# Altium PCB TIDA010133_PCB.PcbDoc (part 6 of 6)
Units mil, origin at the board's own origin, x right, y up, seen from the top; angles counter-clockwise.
Board outline 4100 x 6400 mil, 8 copper layers (Top Layer, Ground 1, Signal 1, Power 1, Ground 2, Signal 2, Power 2, Bottom Layer), stack 60.4 mil thick; 587 components, 322 nets, 1661 pads, 859 vias.
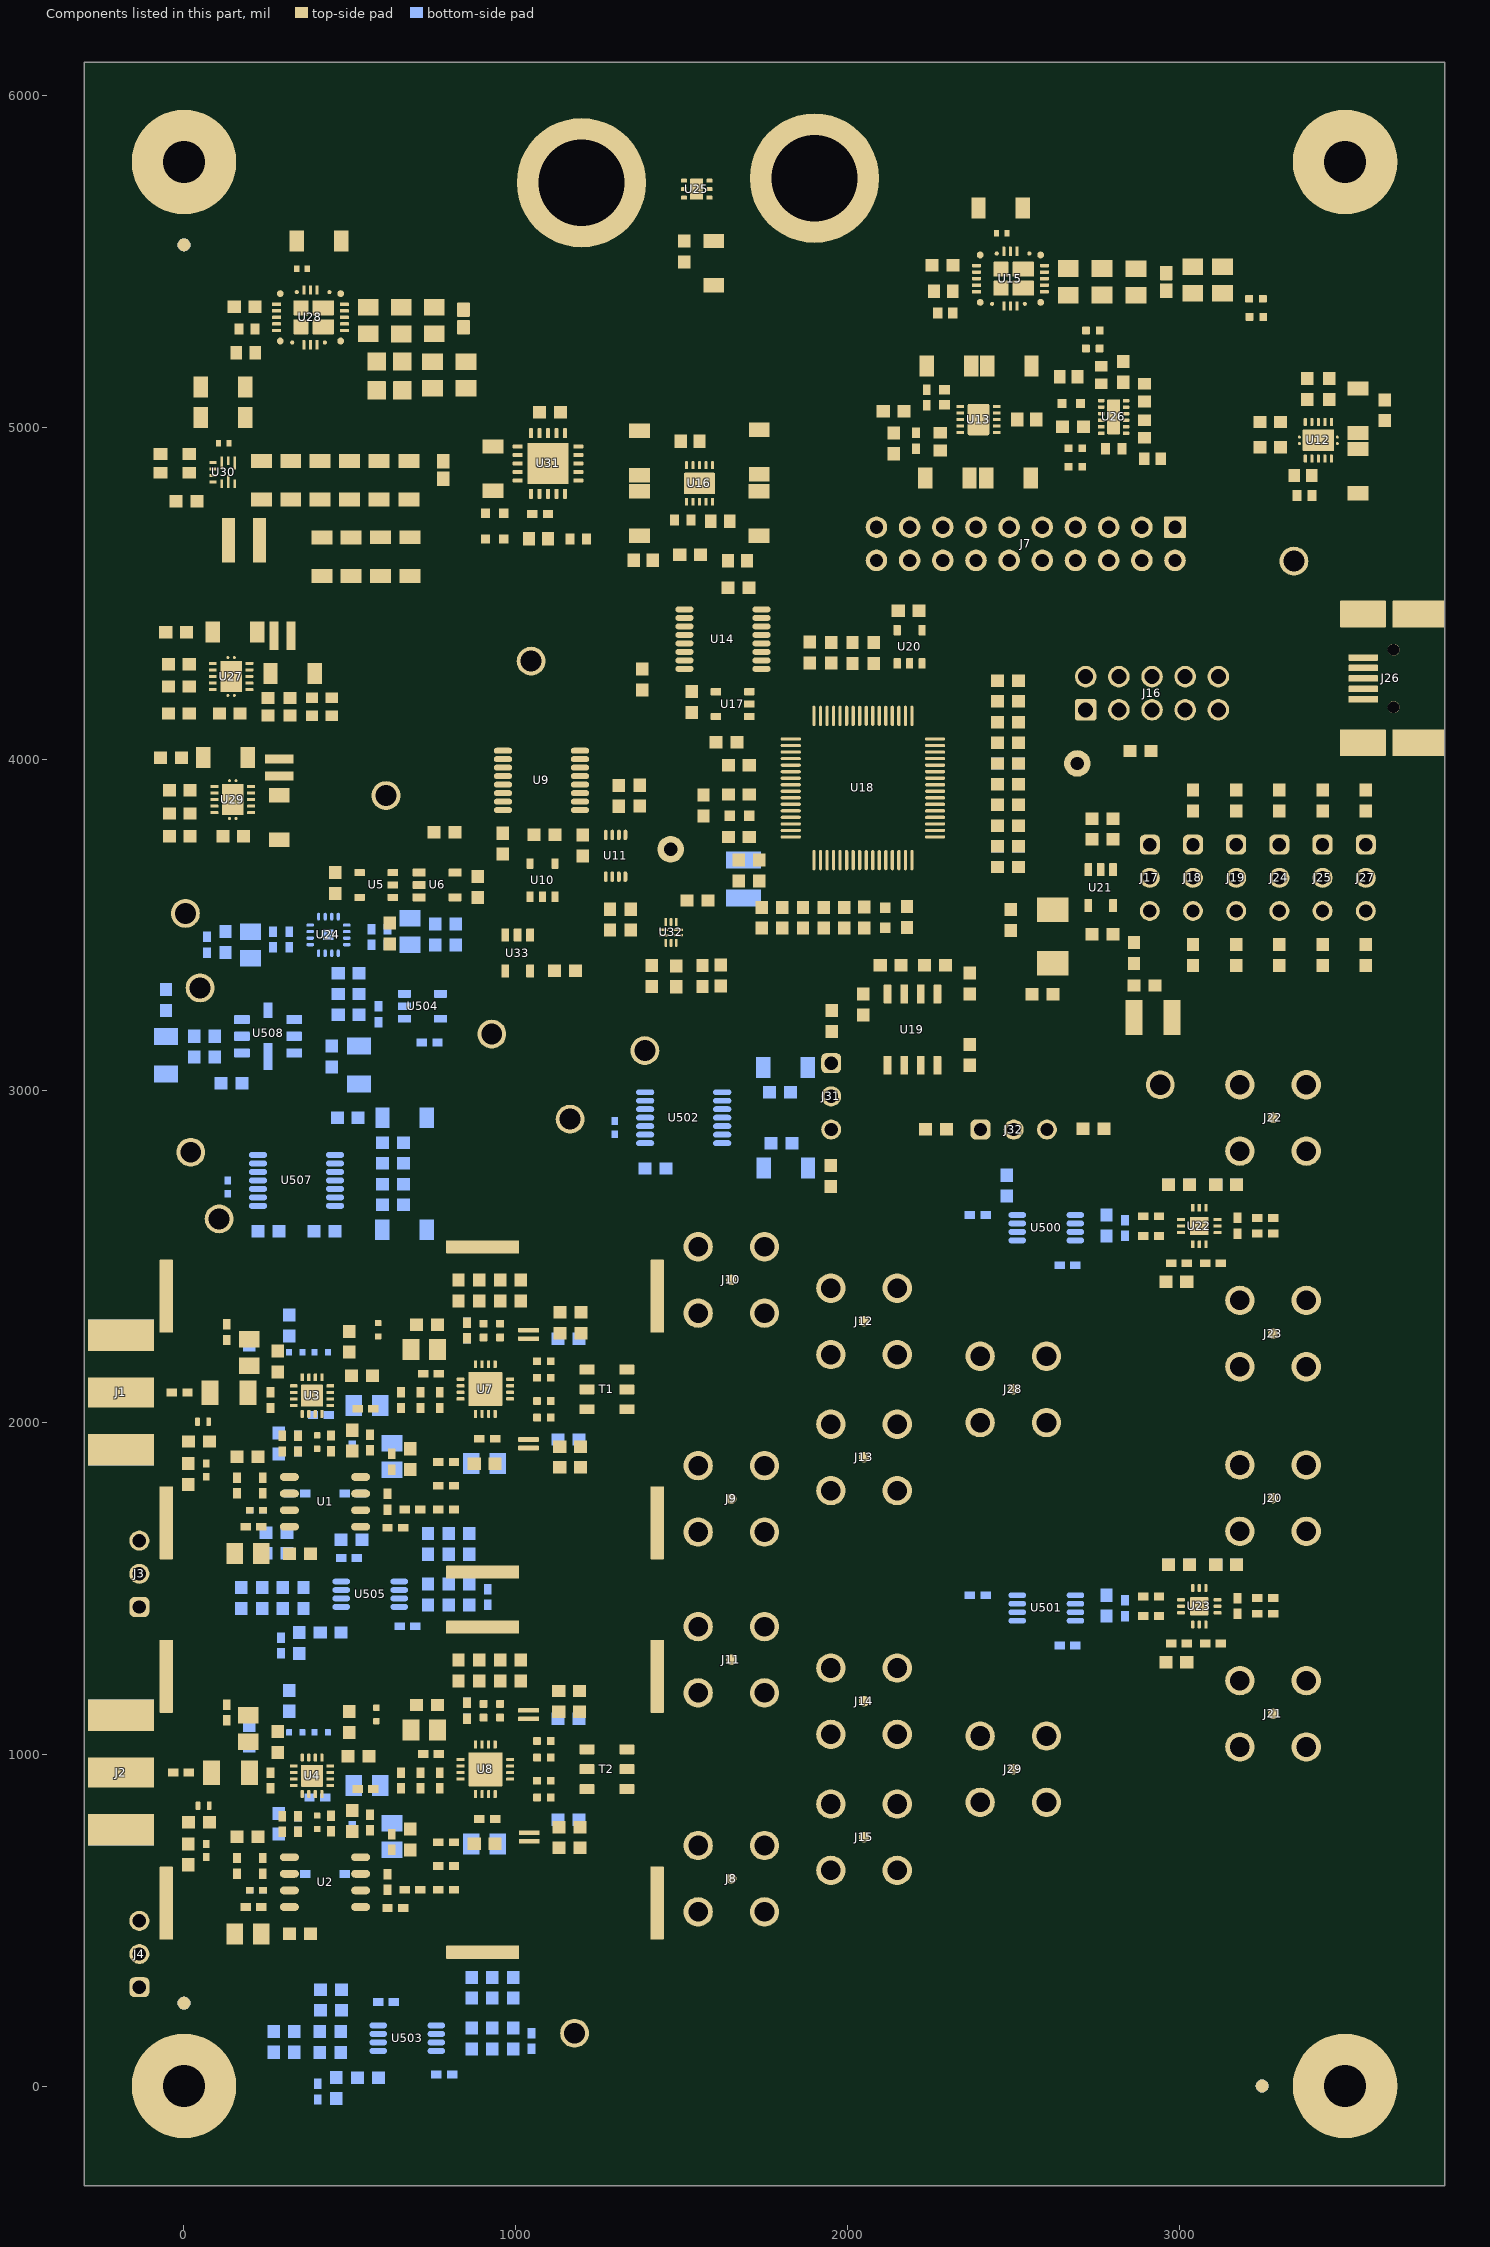
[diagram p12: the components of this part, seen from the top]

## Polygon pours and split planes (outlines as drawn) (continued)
-5VA_C on Bottom Layer "BOTTOM_LAYER_-5VA_C_P52956" (solid, remove dead copper, pour order 52956): 440.15,1514.5 422.78,1531.87 422.78,1661.81 431.2,1670.22 489.4,1670.22 495.95,1663.66 495.95,1559.31 503.46,1551.81 503.46,1517.34 500.62,1514.5
+5VA_LMH6518_1 on Bottom Layer "BOTTOM_LAYER_+5VA_LMH6518_1_P52954" (solid, remove dead copper, pour order 52954): 794.49,2169.85 824.25,2169.85 831.96,2162.14 870.59,2162.14 880.21,2171.76 880.21,2269.39 875.52,2274.08 789.16,2274.08 782.88,2267.8 782.88,2181.45
+5VA_LMH6518_2 on Bottom Layer "BOTTOM_LAYER_+5VA_LMH6518_2_P52953" (solid, remove dead copper, pour order 52953): 794.49,1023.59 824.25,1023.59 831.96,1015.88 870.59,1015.88 880.21,1025.5 880.21,1123.14 875.52,1127.82 789.17,1127.82 782.88,1121.54 782.88,1035.2
-5VA_C on Bottom Layer "BOTTOM_LAYER_-5VA_C_P52952" (solid, remove dead copper, pour order 52952): 534.74,295.76 541.67,302.69 598.33,302.69 609.29,291.7 609.29,222.3 616.08,215.51 616.08,179.53 612.49,175.94 552.94,175.94 534.74,194.15
+5VA_C on Bottom Layer "BOTTOM_LAYER_+5VA_C_P52950" (solid, remove dead copper, pour order 52950): 602.86,1444.55 609.04,1450.73 675.82,1450.73 678.92,1447.63 678.92,1421.8 670.04,1412.93 670.04,1337.83 661.16,1328.96 614.86,1328.96 602.86,1340.95
-5VA_C on Bottom Layer "BOTTOM_LAYER_-5VA_C_P52951" (solid, remove dead copper, pour order 52951): 2661.41,1409.23 2712.78,1409.23 2714.56,1407.46 2714.56,1253.78 2706.77,1245.99 2673.5,1245.99 2665.29,1254.2 2665.29,1350.03 2657.74,1357.58 2657.74,1405.56
+5VA_C on Bottom Layer "BOTTOM_LAYER_+5VA_C_P52949" (solid, remove dead copper, pour order 52949): 721.14,107.12 726.44,112.42 787.41,112.42 790.44,109.38 790.44,83.29 781.78,74.62 781.78,-5.48 774.69,-12.57 725.26,-12.57 721.14,-8.44
3P3USB on Bottom Layer "BOTTOM_LAYER_3P3USB_P52948" (solid, remove dead copper, pour order 52948): 2389.18,3963.19 2397.96,3954.41 2475.72,3954.41 2483.93,3962.63 2483.93,4024.59 2476.2,4032.32 2394.73,4032.32 2389.18,4026.77
GND on Bottom Layer "BOTTOM_LAYER_GND_P52947" (solid, remove dead copper, pour order 52947): 370.51,2006.73 405.93,2006.73 413.44,2014.24 413.44,2040.19 421.44,2048.18 421.44,2110.2 413.84,2117.79 356.83,2117.79 351.95,2112.91 351.95,2025.21
-5VA_C on Bottom Layer "BOTTOM_LAYER_-5VA_C_P52945" (solid, remove dead copper, pour order 52945): 2661.3,2555.38 2712.89,2555.38 2714.56,2553.71 2714.56,2437.76 2701.48,2424.68 2670.53,2424.68 2665.29,2429.92 2665.29,2496.28 2657.74,2503.83 2657.74,2551.82
GND on Bottom Layer "BOTTOM_LAYER_GND_P52946" (solid, remove dead copper, pour order 52946): 370.51,860.47 395.69,860.47 398.09,862.88 398.09,878.58 421.44,901.93 421.44,963.94 413.84,971.54 356.83,971.54 351.95,966.65 351.95,878.95
+5VA_TLV3605_2 on Bottom Layer "BOTTOM_LAYER_+5VA_TLV3605_2_P52944" (solid, remove dead copper, pour order 52944): 3008.66,1550.01 3057.91,1550.01 3066.8,1558.9 3066.81,1622.75 3052.27,1637.28 3012.69,1637.28 3000.57,1625.17 3000.57,1558.1
+5VA_TLV3605_1 on Bottom Layer "BOTTOM_LAYER_+5VA_TLV3605_1_P52943" (solid, remove dead copper, pour order 52943): 3010.87,2697.52 3061.33,2697.52 3066.8,2702.99 3066.81,2769.01 3052.27,2783.54 3012.69,2783.54 3000.57,2771.42 3000.57,2707.82
2.5V_DACREF1 on Bottom Layer "BOTTOM_LAYER_2.5V_DACREF1_P52942" (solid, remove dead copper, pour order 52942): 674.02,1689.78 669.18,1684.94 669.18,1647.29 680.47,1636 749.04,1636 759.05,1646.01 759.05,1685.94 755.21,1689.78
+2.5VA_1 on Power 1 "POWER_1_+2.5VA_1_P52907" (solid, remove dead copper, pour order 52907): 1527.46,2779.05 1730.18,2779.05 1730.18,3373.4 1464.3,3639.28 1197.72,3639.28 1197.72,3108.79
+8VA on Power 1 "Power-+8VA" (solid, remove dead copper, pour order 52916): 33 vertices, not listed, extent -300,-300 1876,5091.13
-5VA on Power 1 "POWER_1_-5VA_P52981" (solid, remove dead copper, pour order 52981): 46 vertices, not listed, extent 225.89,-300 3800,5015.49
+3P3VD on Power 1 "Power-+3P3VD" (solid, remove dead copper, pour order 52918): 44 vertices, not listed, extent 1459,1152.89 3800,5368.63
+12VA on Power 1 "POWER_1_+12VA_P52917" (solid, remove dead copper, pour order 52917): 18 vertices, not listed, extent -300,5281.57 3800,6100
-3.3VA on Power 1 "Power--3.3VA" (solid, remove dead copper, pour order 52915): 41 vertices, not listed, extent 485.59,838.53 2133.79,4776.43
-2.5VA on Power 1 "Power--2.5VA" (solid, remove dead copper, pour order 52914): 22 vertices, not listed, extent -300,2727.98 2701.64,5303.74
VREGIN on Power 1 "POWER_1_VREGIN_P52913" (solid, remove dead copper, pour order 52913): 2122.2,3612.88 2149.75,3585.33 2942.2,3585.33 2969.75,3612.88 2969.75,3672.8 2957.46,3685.08 2638.55,3685.08 2609.13,3714.5 2609.13,4391.89 2558.31,4442.7 1972.96,4442.7 1669.88,4139.61 1669.88,3816.74 1873.73,3612.88
+3P3VD on Power 1 "POWER_1_+3P3VD_P52912" (solid, remove dead copper, pour order 52912): 843.9,1873.49 1185.95,1873.49 1227,1832.44 1227,1559.95 1227,1246.41 1227,656.49 1189.84,619.33 783.38,619.33 762.89,639.82 762.89,1666.54 831.44,1735.09 831.15,1860.75
-5VA_C on Power 1 "POWER_1_-5VA_C_P52911" (solid, remove dead copper, pour order 52911): 2501.72,1265.56 2608.64,1158.64 2823.48,1158.64 2854.94,1190.1 2854.94,2376.61 2701.59,2529.96 2518.77,2529.96 2501.72,2512.91
LM27762_IN on Power 1 "Power-LM27762_IN" (solid, remove dead copper, pour order 52910): 22 vertices, not listed, extent 2221.71,4773.87 3202.89,5610
+5.5V_IN_TPS7A94 on Power 1 "POWER_1_+5.5V_IN_TPS7A94_P52909" (solid, remove dead copper, pour order 52909): 17 vertices, not listed, extent -79.19,3854.7 626.89,5084.15
+5VA_C on Power 1 "POWER_1_+5VA_C_P52908" (solid, remove dead copper, pour order 52908): 2476.06,2655.64 2476.06,1501.03 2454.48,1479.45 2217.62,1479.45 2174.41,1522.65 2174.41,2675.78 2202.17,2703.54 2428.16,2703.54
+5VA on Power 2 "POWER_2_+5VA_P52935" (solid, remove dead copper, pour order 52935): 62 vertices, not listed, extent -58.98,264.7 2999.9,5111.69
+2.5VA on Power 2 "Power/Ground 2-+2.5VA" (solid, remove dead copper, pour order 52934): 19 vertices, not listed, extent -300,2464.85 3800,6100
-5VA_C on Power 2 "POWER_2_-5VA_C_P52933" (solid, remove dead copper, pour order 52933): 33 vertices, not listed, extent -300,-300 2877.85,1702.77
2.5V_DACREF1 on Power 2 "POWER_2_2.5V_DACREF1_P52932" (solid, remove dead copper, pour order 52932): 59 vertices, not listed, extent -294.45,10.39 878.71,3364.85
+5VA_C on Power 2 "POWER_2_+5VA_C_P52931" (solid, remove dead copper, pour order 52931): 641.31,0.09 711.37,-69.98 1446.01,-69.98 2188.09,-69.98 2447.41,189.34 2447.41,1254 2532.6,1339.19 2532.6,1577.96 2471.65,1638.9 2058.19,1638.9 2027.16,1607.87 2027.16,589.31 1682.23,244.38 689.5,244.38 641.31,196.18
1P8V_USB on Power 2 "POWER_2_1P8V_USB_P52930" (solid, remove dead copper, pour order 52930): 1405.82,3659.84 1405.82,3838.46 1627.96,4060.6 1627.96,4298.58 1657.51,4328.13 2319.87,4328.13 2362.2,4285.8 2362.2,3656.28 2344.3,3638.38 1427.16,3638.38
+3P3VD on Power 2 "POWER_2_+3P3VD_P52929" (solid, remove dead copper, pour order 52929): 20 vertices, not listed, extent 794,3499.54 1603.62,4329.27
-2.5VA on Power 2 "POWER_2_-2.5VA_P52928" (solid, remove dead copper, pour order 52928): 2395.34,5176 2488.72,5269.38 2914.38,5269.38 2965,5320 2965,5570.29 2910.29,5625 2144.95,5625 2026.43,5506.48 2026.43,5208.7 2059.13,5176
+5VA_LMH6518_2 on Power 2 "POWER_2_+5VA_LMH6518_2_P52927" (solid, remove dead copper, pour order 52927): 940.17,622.27 932.9,629.53 932.9,822.68 780.67,974.91 780.67,1165.29 859.33,1243.95 859.33,1318.55 872.79,1332.01 1263.58,1332.01 1288.56,1307.03 1288.56,951.8 1288.56,643.82 1267,622.27
+5VA_LMH6518_1 on Power 2 "POWER_2_+5VA_LMH6518_1_P52926" (solid, remove dead copper, pour order 52926): 1269.29,1771.49 1290.72,1792.92 1290.72,2454.26 1265.74,2479.24 874.95,2479.24 861.49,2465.78 861.49,2391.18 782.83,2312.52 782.83,2122.14 935.06,1969.91 935.06,1851.77 935.06,1784.82 948.39,1771.49
+2.5VA_1 on Power 2 "POWER_2_+2.5VA_1_P52925" (solid, remove dead copper, pour order 52925): 1690.77,2815.56 1697.1,2809.23 1697.1,2633.18 1686.45,2622.53 834.37,2622.53 698.76,2486.93 508.79,2486.93 446.97,2548.74 446.97,2799.21 463.33,2815.56
-2.5VA_1 on Power 2 "POWER_2_-2.5VA_1_P52924" (solid, remove dead copper, pour order 52924): 1712.86,3049.79 1734.78,3027.87 1734.78,2850.25 1716.4,2831.87 454.76,2831.87 446.63,2839.99 446.63,2956.3 492.08,3001.75 1399.4,3001.75 1447.44,3049.79
+8VA_BUF802_1 on Power 2 "POWER_2_+8VA_BUF802_1_P52923" (solid, remove dead copper, pour order 52923): 98.65,2364.96 98.65,2052.38 130.79,2020.23 406.59,2020.23 484.89,2098.53 484.89,2227.34 336.31,2375.91 109.6,2375.91
-3.3VA_BUF802_2 on Power 2 "POWER_2_-3.3VA_BUF802_2_P52922" (solid, remove dead copper, pour order 52922): 289.24,752.89 336.85,705.29 494.67,705.29 503.49,714.1 503.49,936.02 606.1,1038.63 606.1,1107.36 545.06,1168.4 390.04,1168.4 289.24,1067.6
3P3USB on Power 2 "POWER_2_3P3USB_P52921" (solid, remove dead copper, pour order 52921): 2382.28,3915.7 2406.42,3891.57 2742.93,3891.57 2768.09,3916.73 2768.09,4067.59 2751.28,4084.39 2416.98,4084.39 2382.28,4049.69
VBUS on Power 2 "POWER_2_VBUS_P52920" (solid, remove dead copper, pour order 52920): 2699.28,3655.91 2699.28,3725.29 2713.65,3739.66 2840.2,3739.66 2855.82,3724.03 2855.82,3658.8 2843.7,3646.68 2708.51,3646.68
-5VA_C on Signal 2 "SIGNAL_2_-5VA_C_P52941" (solid, remove dead copper, pour order 52941): 18 vertices, not listed, extent 621.25,2261.54 2718.23,3285.11
+5VA_C on Signal 2 "SIGNAL_2_+5VA_C_P52940" (solid, remove dead copper, pour order 52940): 774.16,3227.82 774.16,3106.45 820.97,3059.64 1319.13,3059.64 1756.66,2622.11 2475.52,2622.11 2507.09,2653.67 2507.09,3191.76 2459.87,3238.98 785.32,3238.98
+5VA_C on Signal 2 "SIGNAL_2_+5VA_C_P52939" (solid, remove dead copper, pour order 52939): 518.03,1386 506.03,1373.99 506.03,-23.87 548.74,-66.59 852.29,-66.59 874.49,-44.38 874.49,760.95 747.73,887.71 747.73,1342.57 704.3,1386
-5.5V_IN_TPS7A33 on Signal 2 "SIGNAL_2_-5.5V_IN_TPS7A33_P52937" (solid, remove dead copper, pour order 52937): 1090.91,4632.29 1125.61,4666.99 1125.61,5016.4 1109.61,5032.4 883.05,5032.4 824.15,4973.5 640.64,4973.5 597.03,4929.89 597.03,4816.95 553.01,4772.93 386.81,4772.93 372.16,4758.27 372.16,4643.63 383.5,4632.29
+12VA on Signal 2 "SIGNAL_2_+12VA_P52936" (solid, remove dead copper, pour order 52936): 1546.14,4946.99 1546.14,4908.53 1562.38,4892.29 1677.53,4892.29 1788.36,4892.29 1812.57,4916.5 1812.57,5061.47 1668.34,5205.7 1668.34,5815.85 1652.34,5831.85 1475.9,5831.85 1454.96,5810.91 1454.96,5038.16
TPS62913_IBB_IN on Signal 2 "SIGNAL_2_TPS62913_IBB_IN_P52938" (solid, remove dead copper, pour order 52938): 225.4,4757.48 256.49,4788.57 528.34,4788.57 549.98,4810.21 549.98,5230.15 535.94,5244.19 239.28,5244.19 169,5314.47 6.39,5314.47 -98.33,5209.74 -98.33,4777.88 -77.93,4757.48
GND on Ground 1 "Top Layer-GND" (solid, remove dead copper, pour order 52906): -300,6100 -300,-300 3800,-300 3800,6100 3796.44,6100
GND on Ground 2 "Top Layer-GND" (solid, remove dead copper, pour order 52919): -300,6100 -300,-300 3800,-300 3800,6100 3796.44,6100

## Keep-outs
Keep-Out Layer:
  the board outline again, w50
  text ".Layer_Name" at -723,-1798.49 h60

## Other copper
Top Layer:
  pour cut-out: 988.81,2454.02 980.1,2445.31 980.1,2397.43 989.24,2388.38 ccw(c990.91,2390.62) 990.91,2387.83 1053.49,2387.83 ccw(c1053.49,2408.81) 1074.47,2408.81 1074.47,2436.79 ccw(c1057.24,2436.79) 1057.24,2454.02
  pour cut-out: 1172.32,1111.44 1172.32,1097.31 1174.24,1095.39 1213.38,1095.39 1223,1105.01 1223,1116 1176.88,1116
  pour cut-out: 652.61,4636.35 645.61,4629.35 645.61,4593.35 651.61,4587.35 715.61,4587.35 718.61,4590.35 718.61,4631.35 713.61,4636.35 660.61,4636.35
  pour cut-out: 563.61,4637.35 556.61,4630.35 556.61,4594.35 562.61,4588.35 626.61,4588.35 629.61,4591.35 629.61,4632.35 624.61,4637.35 571.61,4637.35
  pour cut-out: 474.61,4636.35 467.61,4629.35 467.61,4593.35 473.61,4587.35 537.61,4587.35 540.61,4590.35 540.61,4631.35 535.61,4636.35 482.61,4636.35
  pour cut-out: 386.61,4637.35 379.61,4630.35 379.61,4594.35 385.61,4588.35 449.61,4588.35 452.61,4591.35 452.61,4632.35 447.61,4637.35 394.61,4637.35
  pour cut-out: -79.77,965.48 -79.77,621.96 -65.97,608.17 58.22,608.17 102.32,564.08 476.51,564.08 495.47,583.04 495.47,699.04 484.92,709.6 371.69,709.6 359.87,721.42 359.87,782.7 353.88,788.69 330.06,788.69 327.1,791.65 327.1,849.05 340.42,862.37 340.42,889.61 349.97,899.16 419.23,899.16 421.29,901.22 421.29,967.68 417.86,971.11 354.84,971.11 340.93,957.2 291.78,957.2 262.98,986 -59.25,986
  pour cut-out: -79.63,2111.74 -79.63,1768.22 -65.84,1754.42 58.36,1754.42 102.45,1710.33 476.64,1710.33 495.61,1729.3 495.61,1845.3 485.05,1855.85 371.83,1855.85 360.01,1867.67 360.01,1928.95 354.02,1934.94 330.2,1934.94 327.24,1937.9 327.24,1995.31 340.56,2008.63 340.56,2035.87 350.1,2045.41 419.37,2045.41 421.42,2047.47 421.42,2113.94 417.99,2117.37 354.97,2117.37 341.06,2103.46 291.91,2103.46 262.37,2133 -58.37,2133
  pour cut-out: 1222.3,1168.31 1222.3,1149.72 1210.74,1138.16 1163.77,1138.16 1163.77,1164.76 1171.18,1172.16
  pour cut-out: 1220.03,2318.64 1225.88,2312.79 1225.88,2285.58 1180.47,2285.58 1171.77,2276.88 1171.77,2302.94 1187,2318.17 1219.91,2318.17
  pour cut-out: 708.06,1205.26 780.28,1277.48
  pour cut-out: 579.86,749.35 579.86,872.34 589.41,881.89 589.41,906.59 586.02,909.98 586.02,950.73 576.66,960.08 548.23,960.08 541.69,966.63 541.69,1010.57 547,1015.88 940.64,1015.88 949.36,1024.61 949.36,1051.65 967.49,1069.78 967.49,1188.04 974.5,1195.04 1057.7,1195.04 1071.96,1180.78 1071.96,1125.86 1068.17,1122.06 1005.24,1122.06 994.76,1111.58 994.76,1054.01 967.59,1026.84 967.59,908.43 960.22,901.05 935.46,901.05 930.13,895.73 930.13,863.83 941.74,852.22 941.74,837.08 935.46,830.81 922.6,830.81 913.55,821.76 913.55,763.09 904.3,753.84 855.83,753.84 848.64,746.65 848.64,695.89 832.64,679.88 786.71,679.88 728.71,737.88 591.04,737.88 580.4,748.52
  pour cut-out: 579.86,1895.6 579.86,2018.6 589.41,2028.14 589.41,2052.85 586.02,2056.24 586.02,2096.98 576.66,2106.34 548.23,2106.34 541.69,2112.88 541.69,2156.83 547,2162.14 940.64,2162.14 949.36,2170.86 949.36,2197.9 967.49,2216.03 967.49,2334.29 974.5,2341.3 1057.7,2341.3 1071.96,2327.03 1071.96,2272.11 1068.17,2268.32 1005.24,2268.32 994.76,2257.84 994.76,2200.27 967.59,2173.1 967.59,2054.68 960.22,2047.31 935.46,2047.31 930.13,2041.98 930.13,2010.08 941.74,1998.48 941.74,1983.34 935.46,1977.06 922.59,1977.06 913.55,1968.02 913.55,1909.34 904.3,1900.09 855.83,1900.09 848.64,1892.91 848.64,1842.14 832.64,1826.14 786.71,1826.14 728.71,1884.14 591.04,1884.14 580.4,1894.77
  text "1" at 3057.15,-43 h60
  text ".Layer_Name" at -723,-1798.49 h60
Ground 1:
  text "2" at 3041.4,-48.72 h60
  text ".Layer_Name" at -711.37,-1800 h60
Power 1:
  text "4" at 3041.4,-49.98 h60
  text ".Layer_Name" at -705.64,-1802.34 h60
Ground 2:
  text "5" at 3037.62,-47.46 h60
  text ".Layer_Name" at -713.29,-1796.6 h60
Power 2:
  pour cut-out: 1678.07,4742.11 1626.27,4742.11 1624.07,4744.3 1624.07,4771.85 1643.51,4791.3 1656.45,4791.3 1664.99,4782.76 1678.53,4782.76 1690.31,4770.99 1690.31,4754.34
  text "7" at 3041.4,-48.72 h60
  text ".Layer_Name" at -714.24,-1796.59 h60
Signal 1:
  text "3" at 3043.92,-44.94 h60
  text ".Layer_Name" at -723,-1798.49 h60
Signal 2:
  text "6" at 3043.86,-51.2 h60
  text ".Layer_Name" at -723,-1798.49 h60
Bottom Layer:
  pour cut-out: 3000.34,2661.04 3000.34,2694.4 3004.96,2699.02 3031.15,2699.02 3040.94,2689.22 3040.94,2658.3 3038.19,2655.55 3004.58,2655.55 3000.98,2659.15
  pour cut-out: 3002.3,1503.62 3002.3,1536.98 3006.91,1541.59 3033.11,1541.59 3042.9,1531.8 3042.9,1500.88 3040.14,1498.12 3006.54,1498.12 3002.94,1501.72
  text "8" at 3072.48,-44.08 h60
  text ".Layer_Name" at -723,-1798.49 h60

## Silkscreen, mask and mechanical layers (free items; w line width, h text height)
Top Overlay:
  drawing of 294 lines, arcs and shapes, not listed
  text "+3.3VD" at 3255.38,4474.74 h30
  text "USB2ANY I/F" at 2673.79,4328.36 h30
  text "GND" at 996.34,4169.88 h30
  text "3P3USB" at 2791.99,3891.78 h30 r90
  text "+8VA" at 551.57,3772.24 h30
  text "1" at 3634.94,3723.53 h30
  text "1P8V_USB" at 1362.14,3623.21 h30
  text "3" at 3625.68,3524.78 h30
  text "GND" at 123.58,3497.81 h30 r90
  text "+5VA" at 169.8,3250.4 h30 r90
  text "-5VA" at 1044.14,3110.17 h30 r90
  text "GND" at 1507.45,3070.45 h30 r90
  text "GND" at 2904.21,2901.68 h30
  text "Prog." at 1573.75,2850.76 h25
  text "J25" at 1386.05,2849.36 h25
  text "J31" at 1477.84,2849.19 h25
  text "-3.3VA" at 1073.03,2794.19 h30
  text "0" at 1405.46,2785.11 h25
  text "0" at 1496.41,2785.11 h25
  text "FTDI" at 1584.53,2783.23 h25
  text "Prog." at 2562.09,2740.21 h25
  text "J18" at 2003.37,2738.84 h25
  text "Device" at 2306.12,2739.46 h25
  text "J19" at 2088.93,2738.22 h25
  text "J24" at 2172.62,2738.09 h25
  text "-2.5VA" at 140.54,2727.25 h30 r90
  text "1" at 1408.13,2725.85 h25
  text "USB2ANY" at 1582.08,2721.86 h25
  text "1" at 1497.64,2720.92 h25
  text "CH1_TRIGGER_OUTP" at 3524.51,2714.48 h30 r90
  text "D" at 543.46,2697.44 h25
  text "x" at 2023.66,2683.59 h25
  text "LMH6518" at 2268.37,2681.97 h25
  text "FTDI" at 2552.75,2681.06 h25
  text "0" at 2197.97,2679.85 h25
  text "0" at 2110.33,2679.16 h25
  text "1" at 2114.77,2615.6 h25
  text "0" at 2198.53,2615.6 h25
  text "LMH6518_CH1" at 2264.6,2614.07 h25
  text "0" at 2027.49,2612.83 h25
  text "USB2ANY" at 2551.32,2611.21 h25
  text "1" at 2031.24,2548.87 h25
  text "1" at 2115.92,2547.5 h25
  text "0" at 2197.83,2546.11 h25
  text "LMH6518_CH2" at 2264.98,2546.16 h25
  text "USB2ANY" at 2551.69,2542.27 h25
  text "+2.5VA" at 223.65,2535.92 h30 r90
  text "E" at 1325.44,2531.35 h25
  text "CH1" at -230.68,2403.32 h30
  text "E" at 1068.53,2382.91 h25
  text "F" at 1161.35,2197.69 h25
  text "D" at 621.17,2135.33 h25
  text "CH1_TRIGGER_OUTN" at 3522.62,2082.62 h30 r90
  text "F" at 1232.86,1773.29 h25
  text "J10: CH1_OUT+ / J9: CH1_OUT- / J12: CH1_OUT_T+ / J13: CH1_OUT_T- / J28: CH1_OUT_CM" at 2297,1571 h30
  text "CH2_TRIGGER_OUTP" at 3525.15,1551.34 h30 r90
  text "B" at 1301.09,1495.01 h25
  text "A" at 337.33,1474.61 h25
  text "B" at 1071.08,1281.08 h25
  text "CH2" at -235.04,1252.86 h30
  text "C" at 1170.62,1052.15 h25
  text "A" at 611.28,988.06 h25
  text "CH2_TRIGGER_OUTN" at 3520.39,941.41 h30 r90
  text "C" at 1213.4,617.33 h25
  text "J11: CH2_OUT+ / J8: CH2_OUT- / J14: CH2_OUT_T+ / J15: CH2_OUT_T- / J29: CH2_OUT_CM" at 2289,384 h30
  text "'.PRJ_Title'_REV.PCB_Rev" at 1856.1,152.9 h110
  text "GND" at 1142.81,36.72 h30
  text "CCA REV [ ]" at 389.98,-74.95 h60
  text "'.CCA REV'" at 899.22,-81.34 h110
  text "ESD REV [ ]" at 392.04,-197.65 h60
  text "'.ESD REV'" at 902.84,-199.15 h110
  text ".Layer_Name" at -723,-1798.49 h60
Bottom Overlay:
  circle w14: c2732.61,2626.44 r2.35
  circle w14: c2732.61,1480.18 r2.35
  circle w14: c1343.92,2825.17 r2.35
  circle w14: c539.1,104.9 r2.35
  circle w14: c621.3,3216.4 r2.35
  circle w14: c422.11,1445.25 r2.35
  circle w14: c519.38,3403.76 r2.35
  circle w14: c184.33,2621.02 r2.35
  circle w6: c334.65,258.66 r25
  circle w6: c163.69,345.93 r25
  lines w6: -4.08,1521.78 6,1531.87 132.72,1531.87 ; 108.77,3207.11 108.77,3242.13 ; 171.79,738.97 176.95,733.8 249.44,733.8 ; 176.32,1891.2 183.4,1884.13 247.34,1884.13 ; 198.77,1599.89 198.77,1606.95 205.85,1614.04 ; 297.19,350.63 297.19,279.99 281.69,264.49 141.65,264.49 126.58,279.56 126.58,488.45 141.76,503.63 279.19,503.63 297.19,485.63 297.19,416.63 ; 317.25,2175.86 317.25,2189.94 ; 318.62,1025.61 318.62,1046.98 ; 333.9,2032.49 341.19,2025.21 351.95,2025.21 ; 371.82,210.49 371.82,71.91 378.88,64.86 502.77,64.86 514.86,76.94 514.86,323.44 506.94,331.36 382.26,331.36 371.82,320.91 371.82,310.35 ; 400.02,3332.17 409.36,3332.17 427.01,3314.53 ; 441.14,902.83 441.14,963.53 ; 565.15,1394.34 565.15,1406.94 ; 619.39,3180.19 631.2,3168.38 631.2,3161.42 ; 631.22,3527.29 631.22,3586.77 ; 678.6,47.92 678.6,68.66 ; 696.05,1327.28 696.05,1351.75 ; 727.83,1710.94 727.83,1722.69 740.68,1735.54 887.22,1735.54 894.04,1728.72 ; 764.95,3545.52 764.95,3554.8 774.22,3564.07 ; 807.77,-9.47 807.77,3.39 ; 946.3,1531.45 964.97,1550.12 1089.91,1550.12 1101.96,1538.08
  text "G" at 173.19,333.8 h25
  text "G" at 344.15,246.54 h25
  text ".Layer_Name" at -723,-1798.49 h60
Top Paste:
  text ".Layer_Name" at -723,-1798.49 h60
Bottom Paste:
  text ".Layer_Name" at -723,-1798.49 h60
Top Solder:
  text ".Layer_Name" at -723,-1798.49 h60
  text ".Layer_Name" at -723,-1798.49 h60
Bottom Solder:
  text ".Layer_Name" at -723,-1798.49 h60
Drill Guide:
  text ".Layer_Name" at -723,-1798.49 h60
M1 Board Outline:
  the board outline again, w10
  text ".Layer_Name" at -723,-1798.49 h60
M2 Board Dimensions:
  rectangle: -1300,-1215 -1175,-1090
  rectangle: -1175,-1340 -800,-1215
  lines w7: -1300,-1215 -300,-1215 ; -1175,-1340 -1175,-1090 ; -1050,-1340 -1050,-1090 ; -800,-1340 -800,-1090 ; -550,-1340 -550,-1090 ; -1300,-1340 -300,-1340 -300,-1090 -1300,-1090 -1300,-1340
  lines w10: -300,-300 3800,-300 3800,6100 -300,6100 -300,-300
M3 3D STEP Top:
  text ".Layer_Name" at -723,-1798.49 h60
M4 3D STEP Bottom:
  text ".Layer_Name" at -723,-1798.49 h60
M5 Assembly Top:
  drawing of 156 lines, arcs and shapes, not listed
  text "R82" at 2258.54,5398.45 h20
  text "R80" at 2266.42,5333.8 h20
  text "R169" at 157.5,5286.43 h20
  text "R171" at 149.32,5214.59 h20
  text "R98" at 2641.27,5143.67 h20
  text "R99" at 2775.18,5130.21 h20 r90
  text "C114" at 2905.85,5067.23 h20 r90
  text "R87" at 2303.69,5062.27 h20 r90
  text "C53" at 2511.62,5010.64 h20
  text "C119" at 2906.82,4954.34 h20 r90
  text "C80" at 1494.19,4947.91 h20
  text "R83" at 2288.37,4931.49 h20 r90
  text "R90" at 2781.63,4924.07 h20
  text "R91" at 2900.06,4895.1 h20
  text "R178" at 25.14,4857.45 h20 r90
  text "R175" at -59.84,4856.03 h20 r90
  text "C22" at 3346.62,4843.28 h20
  text "C117" at 238.92,4807.17 h20 r90
  text "C126" at 500.26,4806.44 h20 r90
  text "C127" at 598.75,4806.45 h20 r90
  text "C118" at 326.13,4805.39 h20 r90
  text "C128" at 681.96,4805.05 h20 r90
  text "C125" at 418.43,4802.29 h20 r90
  text "R77" at 3352.34,4781.28 h20
  text "R108" at 1469.29,4708.33 h20
  text "R103" at 1582.34,4707.25 h20
  text "R177" at 1035.13,4653.51 h20
  text "R179" at 1155.85,4652.55 h20
  text "L16" at 151.13,4647.9 h20
  text "C69" at 1643.54,4589.49 h20
  text "C77" at 1362.28,4586.8 h20
  text "C133" at 328.15,4122.63 h20 r90
  text "R116" at 393.25,4122.63 h20 r90
  text "C132" at 262.08,4121.66 h20 r90
  text "R117" at 458.34,4120.69 h20 r90
  text "MP1" at 609.92,1571.72 h20
  text "MP2" at 601.29,417.99 h20
  text "COMPONENTS MARKED 'DNP' SHOULD NOT BE POPULATED." at -146.5,-1258.5 h60
  text "ASSEMBLY VARIANT:" at -147,-1374 h60
  text ".VariantName" at 889,-1374 h60
  text "PCB VIEWED FROM TOP SIDE" at -1528.5,-1595.67 h60
  text "BOARD #:" at 948,-1595.67 h60
  text ".PRJ_Number" at 1493.5,-1595.67 h60
  text "REV:" at 2338,-1595.67 h60
  text ".PCB_Rev" at 2629.5,-1595.67 h60
  text "SVN REV:" at 3176,-1595.67 h60
  text ".VersionControl_RevNumber" at 3682,-1595.67 h60
  text "TID #:" at 948,-1799 h60
  text ".TID" at 1493.5,-1799 h60
  text ".plot_File_Name" at -856.21,-1994.13 h50
  text "PLOT NAME =" at -1528.5,-2004.34 h60
  text "GENERATED    :" at 950,-2004.34 h60
  text ".Print_Date" at 1819.5,-2004.34 h60
  text ".Print_Time" at 2548.5,-2004.34 h60
  text "TEXAS INSTRUMENTS" at 3813,-2004.34 h60
M6 Assembly Bottom:
  circle w14: c174.68,3114.05 r2.05
  circle w14: c636.28,3216.53 r2.05
  lines w10: -1592.5,-1667.33 5009.5,-1667.33 ; -1590.5,-1870.67 5009.5,-1870.67 ; -184.5,-2080.5 -184.5,-1877.67 ; 437.5,-1667.33 437.5,-1464 ; 1277.5,-1667.33 1277.5,-1464 ; 2544.5,-2074 2544.5,-1464 ; 3433.5,-2074 5009,-2074 5009,-1464 -1592.5,-1464 -1592.5,-2074 1004.5,-2074 5009.5,-2074 5009.5,-1464
  text "COMPONENTS MARKED 'DNP' SHOULD NOT BE POPULATED." at 4802,-1258 h60
  text ".VariantName" at 3758,-1374 h60
  text "ASSEMBLY VARIANT:" at 4797,-1374 h60
  text ".VersionControl_RevNumber" at -264.5,-1596.17 h60
  text "SVN REV:" at 241.5,-1596.17 h60
  text ".PCB_Rev" at 788,-1596.17 h60
  text "REV:" at 1079.5,-1596.17 h60
  text ".PRJ_Number" at 1924,-1596.17 h60
  text "BOARD #:" at 2469.5,-1596.17 h60
  text "PCB VIEWED FROM BOTTOM SIDE" at 4946,-1596.17 h60
  text ".TID" at 1924,-1799.5 h60
  text "TID #:" at 2469.5,-1799.5 h60
  text ".plot_File_Name" at 4268.64,-1990.76 h50
  text "TEXAS INSTRUMENTS" at -395.5,-2004.84 h60
  text ".Print_Time" at 869,-2004.84 h60
  text ".Print_Date" at 1598,-2004.84 h60
  text "GENERATED    :" at 2467.5,-2004.84 h60
  text "PLOT NAME =" at 4946,-2004.84 h60
M9 Title Sheet:
  drawing of 57 lines, arcs and shapes, not listed
  text "1" at -560.16,7096.5 h70
  text "2" at 1935.5,7096.5 h70
  text "3" at 4424.84,7096.5 h70
  text "4" at 6931.51,7096.5 h70
  text "5" at 9430.5,7096.5 h70
  text "6" at 11935.5,7096.5 h70
  text "A" at -1716.5,5953.5 h70
  text "A" at 13083.5,5953.5 h70
  text "B" at -1716.5,3573.5 h70
  text "B" at 13083.5,3573.5 h70
  text "C" at -1716.5,1198.5 h70
  text "C" at 13083.5,1198.5 h70
  text "PROJECT TITLE:" at 10043.5,-662.5 h45
  text ".PRJ_Title" at 10093.5,-795.83 h70
  text "DESIGNED FOR:" at 10043.5,-963.5 h45
  text ".PRJ_Customer" at 10093.5,-1103.5 h70
  text "D" at -1716.5,-1171.5 h70
  text "D" at 13083.5,-1171.5 h70
  text "FILE NAME:" at 10043.5,-1263.5 h45
  text ".PCB_File_Name_No_Path" at 10093.5,-1383.5 h70
  text "Texas Instruments (TI) and/or its licensors do not warrant the accuracy or completeness of this specification" at 5074,-1545.34 h45
  text "ENGINEER:" at 10043.5,-1553.5 h45
  text "LAYOUT BY:" at 11548.5,-1553.5 h45
  text "or any information contained therein. TI and/or its licensors do not warrant that this design will meet" at 5029.01,-1658 h45
  text ".PRJ_Engineer" at 10093.5,-1708.49 h70
  text ".PCB_Layout" at 11599,-1708.49 h70
  text "the specifications, will be suitable for your application or fit for any particular purpose, or will operate in" at 5029.01,-1770.67 h45
  text "ALTIUM DESIGNER VERSION:" at 11548.5,-1863.5 h45
  text "an implementation. TI and/or its licensors do not warrant that the design is production worthy. You should" at 5029.01,-1883.33 h45
  text "completely validate and test your design implementation to confirm the system functionality for your application." at 5074,-1996 h45
  text ".print_Scale" at 10093.5,-1996.83 h70
  text ".Application_BuildNumber" at 11599,-1996.83 h70
  text "1" at -560.16,-2203.5 h70
  text "2" at 1935.5,-2203.5 h70
  text "3" at 4424.84,-2203.5 h70
  text "4" at 6931.51,-2203.5 h70
  text "5" at 9430.5,-2203.5 h70
  text "6" at 11935.5,-2203.5 h70
  text "WO#309716-9714-D" at 12055.73,-2203.93 h70
M10 Fab Notes:
  drawing of 205 lines, arcs and shapes, not listed
  text "FAB NOTES" at 4212.43,6395.78 h60
  text "1. BOARD DIMENSION IS : 4100MIL x 6400MIL" at 4201.05,6229.12 h60
  text "2. VENDOR MAY ADJUST SOLDERMASK WHEREVER SOLDERMASK PADS ARE THE SAME SIZE (1:1) AS PER THE MANUFACTURING CAPABILITIES AND ALL OTHER SOLDER MASK PADS SHALL NOT BE MODIFIED," at 4201.05,6070.77 h60
  text "PROVIDED NO ADJACENT COPPER IS EXPOSED AND NO CONFLICT IS PRODUCED WITH ANY STATED \"VIA TENTING/COVERING\" REQUIREMENTS." at 4320.16,5913.01 h60
  text "3. TRACES WITH 20 MIL TO BE 50 OHMS +/-10% SINGLE ENDED ON TOP LAYER (L1)." at 4201.27,5759.81 h60
  text "4. ALL 10MIL VIAS ARE TENTED ON TOP SIDE UNLESS OTHERWISE SOLDER MASK IS OPENED IN GERBER." at 4198.65,5594.68 h60
  text "5. TRACES WITH 11 MIL AND 6 MIL SPACING TO BE 90 OHMS +/-10% DIFFERENTIAL PAIR ON TOP LAYER (L1)." at 4205.39,5421.19 h60
  text "DESIGN INFORMATION" at 11082.02,5416.17 h60
  text "MIN. TRACK WIDTH:" at 10437.46,5284.05 h60
  text "6" at 11533.7,5284.05 h60
  text "MIL" at 11688.46,5284.05 h60
  text "6. ALL 7.874MIL VIAS ARE TENTED ON BOTTOM SIDE UNLESS OTHERWISE SOLDER MASK IS OPENED IN GERBER." at 4202.2,5256.45 h60
  text "6" at 11537.14,5166.32 h60
  text "MIN. CLEARANCE:" at 10437.46,5159.92 h60
  text "MIL" at 11688.46,5159.92 h60
  text "19.685" at 11330.9,5042.78 h60
  text "MIN. VIA PAD SIZE:" at 10437.46,5035.8 h60
  text "MIL" at 11688.46,5035.8 h60
  text "0.05mm (2MIL)" at 11132.46,4905.9 h60
  text "MINIMUM ANNULAR RING" at 10108.23,4897.67 h60
  text "EXTERNAL" at 11840.46,4897.67 h60
  text "PER" at 10308.23,4787.55 h60
  text "IPC-D-275 CLASS 2 LEVEL C" at 10528.23,4787.54 h60
  text "MIL, HOLES" at 12016.46,4687.07 h60
  text "+/-" at 11624,4678.48 h60
  text "+/-" at 12478,4678.48 h60
  text "REGISTRATION TOLERANCES:" at 10108.23,4677.42 h60
  text "METAL" at 11308,4677.42 h60
  text "5" at 11884.2,4677.42 h60
  text "3" at 12717.2,4677.42 h60
  text "MIL" at 12833.46,4677.42 h60
  text "HOLE SIZE TOLERANCE (UNLESS OTHERWISE SPECIFIED):" at 10108.23,4579.1 h60
  text "+/-" at 12478,4576.23 h60
  text "3" at 12717.2,4575.17 h60
  text "MIL" at 12833.46,4575.17 h60
  text "MATERIAL:" at 10033.46,4437.52 h60
  text "FR-4 High Tg" at 11019.9,4309 h60
  text "X" at 11764.92,4303.53 h60
  text "FR-4" at 12399.62,4303.93 h60
  text "FR-408" at 10454.46,4296.49 h60
  text "OTHER" at 11942.46,4296.49 h60
  text "62 MIL (1.6mm) +/-10%" at 10774.56,4153.46 h60
  text "X" at 10654.46,4151.01 h60
  text "THICKNESS:" at 10108.23,4145.24 h60
  text "OTHER" at 12059.46,4145.24 h60
  text "TOLERANCE:" at 10108.23,4006.92 h60
  text "X" at 10956.46,4006.92 h60
  text "ANSI IPC-6012 TYPE 3 CLASS 2" at 11134.48,4006.92 h60
  text "OTHER +/-" at 11134.46,3862.73 h60
  text "BOW & TWIST:" at 10108.23,3717.54 h60
  text "X" at 10956.46,3717.54 h60
  text "ANSI IPC-6012 TYPE 3 CLASS 2" at 11134.48,3717.54 h60
  text "OTHER +/-" at 11134.46,3570.85 h60
  text "DRILLING:" at 10033.46,3440.23 h60
  text "NC_DRILL FILES" at 11794.46,3335.04 h60
  text "REFERENCE:" at 10108.23,3331.1 h60
  text "X" at 10765.46,3331.01 h60
  text "AS SHOWN" at 10943.46,3331.1 h60
  text "X" at 11666.46,3331.1 h60
  text "OTHER" at 12092.46,3188.85 h60
  text "PTH COPPER THICKNESS:" at 10107.91,3185.32 h60
  text "X" at 11247.14,3185.32 h60
  text "20-30 um" at 11375.14,3185.32 h60
  text "BOARD FINISH:" at 10033.46,3037.73 h60
  text "SILKSCREEN:" at 10188.68,2927.6 h60
  text "X" at 11146.46,2927.6 h60
  text "TOP" at 11263.46,2927.6 h60
  text "X" at 11656.46,2927.6 h60
  text "BOTTOM" at 11774.46,2927.6 h60
  text "SILKSCREEN COLOR:" at 10188.68,2772.41 h60
  text "X" at 11145.46,2772.41 h60
  text "WHITE" at 11263.46,2772.41 h60
  text "OTHER" at 11774.46,2772.41 h60
  text "X" at 11276.46,2628.96 h60
  text "GREEN" at 11394.46,2628.96 h60
  text "OTHER" at 12012.46,2628.96 h60
  text "SOLDER RESIST COLOR:" at 10188.68,2622.1 h60
  text "X" at 11864.36,2476.55 h60
  text "MATTE" at 11394.46,2474.71 h60
  text "SEMI-GLOSS" at 12012,2474.07 h60
  text "IMMERSION GOLD (ENIG)" at 11094.46,2301.94 h60
  text "ENEPIG" at 12432,2294.72 h60
  text "SURFACE FINISH:" at 10033.46,2293.72 h60
  text "X" at 10916.46,2293.72 h60
  text "IMM. TIN/SILVER OR EQUIV" at 10363,2156.4 h60
  text "OTHER" at 11794.46,2152.47 h60
  text "ARRAY/PANEL:" at 10033.46,1997.09 h60
  text "CUT AND TRIM PER M1 BOARD OUTLINE" at 11094.46,1988.87 h60
  text "N.C. ROUTE" at 11094.46,1852.9 h60
  text "V. SCORE" at 11960.46,1852.9 h60
  text "CERTIFICATION:" at 10033.46,1723.77 h60
  text "MATERIALS AND WORKMANSHIP FOR ALL PCBS" at 10758.46,1723.77 h60
  text "TO MEET OR EXCEED THE REQUIREMENTS OF:" at 10758.46,1629.71 h60
  text "X" at 10395.97,1501.08 h60
  text "ANSI IPC-A-600F CLASS ->" at 10523.96,1501.08 h60
  text "X" at 12171.97,1501.08 h60
  text "2" at 12281.96,1501.08 h60
  text "1" at 11966.96,1499.58 h60
  text "3" at 12635.96,1499.58 h60
  text "X" at 11207.97,1353.39 h60
  text "RoHS" at 11335.96,1353.39 h60
  text "OTHER" at 11980.36,1353.39 h60
  text "PER ORDER" at 12377.42,1353.39 h60
  text "ALL BOARDS MUST MEET OR EXCEED UL94-V0 REQUIREMENTS." at 10061,1199.57 h60
  text "PCB MUST BEAR THE UL94V-0 UL REGISTERED MATERIAL ID NUMBER" at 10061,1083.5 h60
  text "ADDITIONAL REQUIREMENTS:" at 10033.46,914.08 h60
  text "MICROSECTION:" at 10108.23,806.95 h60
  text "YES" at 11013.96,806.95 h60
  text "REQUIRED" at 11875.46,662.62 h60
  text "BARE BOARD ELEC. TEST:" at 10108.23,659.76 h60
  text "NONE" at 11413.96,659.76 h60
  text "X" at 11757.46,659.76 h60
  text "PER ORDER" at 12467.46,659.76 h60
  text "XX MIL VIAS REQUIRE NON-CONDUCTIVE FILL AND PLANARIZE" at 10276.38,454.82 h59
  text "XX MIL VIAS REQUIRE CONDUCTIVE FILL AND PLANARIZE" at 10284.38,350.84 h60
  text "OUTER XX MIL TRACES REQUIRE 50 OHM SINGLE-ENDED IMPEDANCE" at 10283.39,187.46 h58
  text "LAYER 2 & 3 (INNER LAYERS) XX MIL WIDE, XX MIL SPACE / TRACES REQUIRE 100 OHM DIFFERENTIAL IMPEDANCE" at 10275.39,-48.26 h60
M11 Gerber Information:
  lines w10: -1592,-1870.17 5008,-1870.17 ; -1592,-1666.83 5010,-1666.83 ; -1592,-1463.5 -1592,-2073.5 2413,-2073.5 5010,-2073.5 5010,-1463.5 -1591.5,-1463.5 -1591.5,-2073.5 -16,-2073.5 ; 873,-2073.5 873,-1463.5 ; 2140,-1666.83 2140,-1463.5 ; 2980,-1666.83 2980,-1463.5 ; 3602,-2080 3602,-1877.17
  text "ALL ARTWORK VIEWED FROM TOP SIDE" at -1528.5,-1595.67 h60
  text "BOARD #:" at 948,-1595.67 h60
  text "'.PRJ_Title'" at 1493.5,-1595.67 h60
  text "REV:" at 2338,-1595.67 h60
  text ".PCB_Rev" at 2629.5,-1595.67 h60
  text "SVN REV:" at 3176,-1595.67 h60
  text ".VersionControl_RevNumber" at 3682,-1595.67 h60
  text "LAYER NAME =" at -1528.5,-1798.49 h60
  text "TID #:" at 948,-1799 h60
  text ".TID" at 1493.5,-1799 h60
  text ".plot_File_Name" at -852.88,-1995 h50
  text "PLOT NAME =" at -1528.5,-2004.34 h60
  text "GENERATED    :" at 950,-2004.34 h60
  text ".Print_Date" at 1819.5,-2004.34 h60
  text ".Print_Time" at 2548.5,-2004.34 h60
  text "TEXAS INSTRUMENTS" at 3813,-2004.34 h60
M12 Stackup:
  drawing of 511 lines, arcs and shapes, not listed
  text "Layer Stackup :" at 4568.69,4667.16 h60
  text "Layer" at 4618.47,4506.85 h60
  text "Name" at 5028.38,4506.85 h60
  text "Material" at 5958.13,4506.85 h60
  text "Thickness" at 6817.89,4506.85 h60
  text "Constant" at 7467.73,4506.85 h60
  text "Board Layer Stack" at 8037.59,4506.85 h60
  text "Top Overlay" at 5028.38,4386.85 h60
  text "Top Solder" at 5028.38,4266.85 h60
  text "Solder Resist" at 5958.13,4266.85 h60
  text "0.80mil" at 6817.89,4266.85 h60
  text "3.5" at 7467.73,4266.85 h60
  text "1" at 4618.47,4146.85 h60
  text "Top Layer" at 5028.38,4146.85 h60
  text "2.10mil" at 6817.89,4146.85 h60
  text "5" at 4261.77,4140.87 h60
  text "3" at 4414.8,4138.83 h60
  text "Dielectric 1" at 5028.38,4026.85 h60
  text "FR-4" at 5958.13,4026.85 h60
  text "11.00mil" at 6817.89,4026.85 h60
  text "4.2" at 7467.73,4026.85 h60
  text "2" at 4618.47,3906.85 h60
  text "Ground 1" at 5028.38,3906.85 h60
  text "1.40mil" at 6817.89,3906.85 h60
  text "Dielectric 2" at 5028.38,3786.85 h60
  text "FR-4" at 5958.13,3786.85 h60
  text "5.00mil" at 6817.89,3786.85 h60
  text "4.2" at 7467.73,3786.85 h60
  text "3" at 4618.47,3666.85 h60
  text "Signal 1" at 5028.38,3666.85 h60
  text "1.40mil" at 6817.89,3666.85 h60
  text "Dielectric 3" at 5028.38,3546.85 h60
  text "FR-4" at 5958.13,3546.85 h60
  text "5.00mil" at 6817.89,3546.85 h60
  text "4.2" at 7467.73,3546.85 h60
  text "4" at 4618.47,3426.85 h60
  text "Power 1" at 5028.38,3426.85 h60
  text "1.40mil" at 6817.89,3426.85 h60
  text "Dielectric 4" at 5028.38,3306.85 h60
  text "FR-4" at 5958.13,3306.85 h60
  text "5.80mil" at 6817.89,3306.85 h60
  text "4.2" at 7467.73,3306.85 h60
  text "5" at 4618.47,3186.85 h60
  text "Ground 2" at 5028.38,3186.85 h60
  text "1.40mil" at 6817.89,3186.85 h60
  text "Dielectric 5" at 5028.38,3066.85 h60
  text "FR-4" at 5958.13,3066.85 h60
  text "5.00mil" at 6817.89,3066.85 h60
  text "4.2" at 7467.73,3066.85 h60
  text "6" at 4618.47,2946.85 h60
  text "Signal 2" at 5028.38,2946.85 h60
  text "1.40mil" at 6817.89,2946.85 h60
  text "Dielectric 6" at 5028.38,2826.85 h60
  text "FR-4" at 5958.13,2826.85 h60
  text "5.00mil" at 6817.89,2826.85 h60
  text "4.2" at 7467.73,2826.85 h60
  text "7" at 4618.47,2706.85 h60
  text "Power 2" at 5028.38,2706.85 h60
  text "1.40mil" at 6817.89,2706.85 h60
  text "Dielectric 7" at 5028.38,2586.85 h60
  text "FR-4" at 5958.13,2586.85 h60
  text "11.00mil" at 6817.89,2586.85 h60
  text "4.2" at 7467.73,2586.85 h60
  text "8" at 4618.47,2466.85 h60
  text "Bottom Layer" at 5028.38,2466.85 h60
  text "2.10mil" at 6817.89,2466.85 h60
  text "Bottom Solder" at 5028.38,2346.85 h60
  text "Solder Resist" at 5958.13,2346.85 h60
  text "0.80mil" at 6817.89,2346.85 h60
  text "3.5" at 7467.73,2346.85 h60
  text "Bottom Overlay" at 5028.38,2226.85 h60
  text "THIS IS AN IMPEDANCE CONTROLLED BOARD" at 5176.36,2044.32 h60
  text "NOTE" at 4627.42,1869.02 h60
  text "1. ALL CORE AND PREPREG THICKNESSES ARE UP TO FAB SHOP TO SELECT." at 4627.42,1742.26 h60
  text "2. EXTERNAL LAYER CU THICKNESSES ARE FINISHED THICKNESS AFTER PLATING." at 4627.42,1615.49 h60
M13 Component Bodies Top:
  text ".Layer_Name" at -723,-1798.49 h60
M14 Component Bodies Bottom:
  text ".Layer_Name" at -723,-1798.49 h60
M15 Courtyards Top:
  text ".Layer_Name" at -723,-1798.49 h60
M16 Courtyards Bottom:
  text ".Layer_Name" at -723,-1798.49 h60
Drill Drawing:
  lines w10: 4451.88,808.69 4569.09,808.69 4569.09,925.88 4451.88,925.88 4451.88,808.69 ; 4453.76,657.99 4453.76,775.17 4570.97,775.17 4570.97,657.99 4453.76,657.99
  lines w15: 4610.37,-547.57 9607.02,-547.57 ; 4610.37,952.43 9607.02,952.43 ; 5161.24,-697.57 5161.24,1102.43 ; 5799.08,-697.57 5799.08,1102.43 ; 7144.68,-697.57 7144.68,1102.43 ; 7650.56,-697.57 7650.56,1102.43 ; 8384.36,-697.57 8384.36,1102.43 ; 4610.37,-697.57 9607.02,-697.57 9607.02,1102.43 4610.37,1102.43 4610.37,-697.57
  text "DRILL TABLE:" at 4619.05,1180.77 h60
  text "Symbol" at 4700.37,997.43 h72
  text "Quantity" at 5206.24,997.43 h72
  text "Finished Hole Size" at 5844.08,997.43 h72
  text "Plated" at 7189.68,997.43 h72
  text "Hole Type" at 7695.56,997.43 h72
  text "Tolerance (mils)" at 8429.36,997.43 h72
  text "83" at 5206.24,847.43 h60
  text "7.87mil (0.200mm)" at 5844.08,847.43 h60
  text "PTH" at 7189.68,847.43 h60
  text "Round" at 7695.56,847.43 h60
  text "+0/-7.87" at 8429.36,847.43 h60
  text "A" at 4671.28,837.44 h66.67
  text "6" at 4484.33,833.43 h60
  text "776" at 5206.24,697.43 h60
  text "10.00mil (0.254mm)" at 5844.08,697.43 h60
  text "PTH" at 7189.68,697.43 h60
  text "Round" at 7695.56,697.43 h60
  text "+0/-10" at 8429.36,697.43 h60
  text "B" at 4671.28,687.44 h66.67
  text "4" at 4486.22,682.72 h60
  text "2" at 5206.24,547.43 h60
  text "35.43mil (0.900mm)" at 5844.08,547.43 h60
  text "NPTH" at 7189.68,547.43 h60
  text "Round" at 7695.56,547.43 h60
  text "+/-2" at 8429.36,547.43 h60
  text "C" at 4671.28,537.44 h66.67
  text "22" at 5206.24,397.43 h60
  text "40.00mil (1.016mm)" at 5844.08,397.43 h60
  text "PTH" at 7189.68,397.43 h60
  text "Round" at 7695.56,397.43 h60
  text "+/-3" at 8429.36,397.43 h60
  text "D" at 4671.28,387.44 h66.67
  text "30" at 5206.24,247.43 h60
  text "40.16mil (1.020mm)" at 5844.08,247.43 h60
  text "PTH" at 7189.68,247.43 h60
  text "Round" at 7695.56,247.43 h60
  text "+/-2" at 8429.36,247.43 h60
  text "E" at 4671.28,237.44 h66.67
  text "10" at 5206.24,97.43 h60
  text "45.28mil (1.150mm)" at 5844.08,97.43 h60
  text "PTH" at 7189.68,97.43 h60
  text "Round" at 7695.56,97.43 h60
  text "+/-3" at 8429.36,97.43 h60
  text "F" at 4671.28,87.44 h66.67
  text "56" at 5206.24,-52.57 h60
  text "59.06mil (1.500mm)" at 5844.08,-52.57 h60
  text "PTH" at 7189.68,-52.57 h60
  text "Round" at 7695.56,-52.57 h60
  text "+/-3" at 8429.36,-52.57 h60
  text "G" at 4671.28,-62.56 h66.67
  text "12" at 5206.24,-202.57 h60
  text "63.00mil (1.600mm)" at 5844.08,-202.57 h60
  text "PTH" at 7189.68,-202.57 h60
  text "Round" at 7695.56,-202.57 h60
  text "+/-3" at 8429.36,-202.57 h60
  text "H" at 4671.28,-212.56 h66.67
  text "4" at 5206.24,-352.57 h60
  text "125.98mil (3.200mm)" at 5844.08,-352.57 h60
  text "PTH" at 7189.68,-352.57 h60
  text "Round" at 7695.56,-352.57 h60
  text "+/-3" at 8429.36,-352.57 h60
  text "I" at 4682.39,-362.56 h66.67
  text "2" at 5206.24,-502.57 h60
  text "259.84mil (6.600mm)" at 5844.08,-502.57 h60
  text "PTH" at 7189.68,-502.57 h60
  text "Round" at 7695.56,-502.57 h60
  text "+/-3" at 8429.36,-502.57 h60
  text "J" at 4671.28,-512.56 h66.67
  text "997 Total" at 5206.24,-652.57 h60
  text "FAB" at -723,-1798.49 h60
M17 Embedded Cavity:
  text ".Layer_Name" at -723,-1798.49 h60
M18 Embedded Assembly:
  text ".Layer_Name" at -723,-1798.49 h60
M19 Embedded Keepout:
  text ".Layer_Name" at -723,-1798.49 h60

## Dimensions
0,0 to -159.51,-160.84 on M2 Board Dimensions
0,0 to -300,6100 on M2 Board Dimensions
-300,-300 to 0,0 on M2 Board Dimensions
0,0 to 3800,-300 on M2 Board Dimensions
-300,-300 to 0,0 on M2 Board Dimensions
-1300,-1340 to -300,-1340 on M2 Board Dimensions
